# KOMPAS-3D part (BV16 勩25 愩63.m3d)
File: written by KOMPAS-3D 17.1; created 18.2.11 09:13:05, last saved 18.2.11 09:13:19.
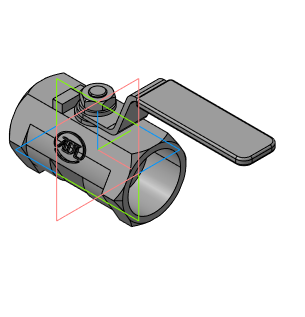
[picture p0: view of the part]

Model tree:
1. Плоскость XY
2. Плоскость ZX
3. Плоскость ZY
4. Ось X
5. Ось Y
6. Ось Z
7. Начало координат
8. Операция без истории:2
